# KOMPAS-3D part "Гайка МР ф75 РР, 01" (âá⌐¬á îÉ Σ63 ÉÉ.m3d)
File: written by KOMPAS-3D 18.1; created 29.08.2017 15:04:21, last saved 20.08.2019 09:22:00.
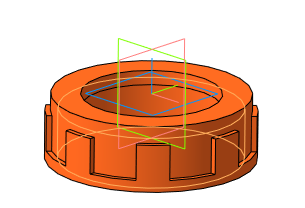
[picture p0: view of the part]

Document properties: Автор: Милов; Организация: Милов; Полное имя файла: D:\1 ПКИ 3D\Полипропиленовые фитинги, трубы\Разборные муфты\Гайка МР ф63 РР.m3d

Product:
- Part/product: Гайка МР ф75 РР  | designation 01
    Материал: Полипропилен  ГОСТ 26996-86 (density 900 kg/m3)
    Масса: 0.0956773
- Part/product: Гайка МР ф63 РР
    Материал: Полипропилен  ГОСТ 26996-86 (density 900 kg/m3)
    Масса: 0.0956773

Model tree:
1. Эскиз:1
2. Операция вращения:1
     Угол 1 = 360
3. Условное изображение резьбы:1  (labels: Tr 100 ·4)
     Длина резьбы = 28; Шаг резьбы = 4; Номинальный диаметр резьбы = 100
4. Подгонка:1
5. Эскиз:2
6. Операция выдавливания:1
     Расстояние 1 = 20
7. Массив по концентрической сетке:1  (with: Операция выдавливания:1, Эскиз:2)  (labels: Полипропилен  ГОСТ 26996-86)  (8 pattern instances)
     Шаг 2 = 360
8. Масштабирование:1  (labels: Полипропилен  ГОСТ 26996-86; 1490845256-394-0-0|0)
     Коэффициент = 1.21359

Expressions: 114/2; 76/2; 96/2; cil4_24737-81
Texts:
  Body Specification ( left align )
  Body Specificaton ( centered )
